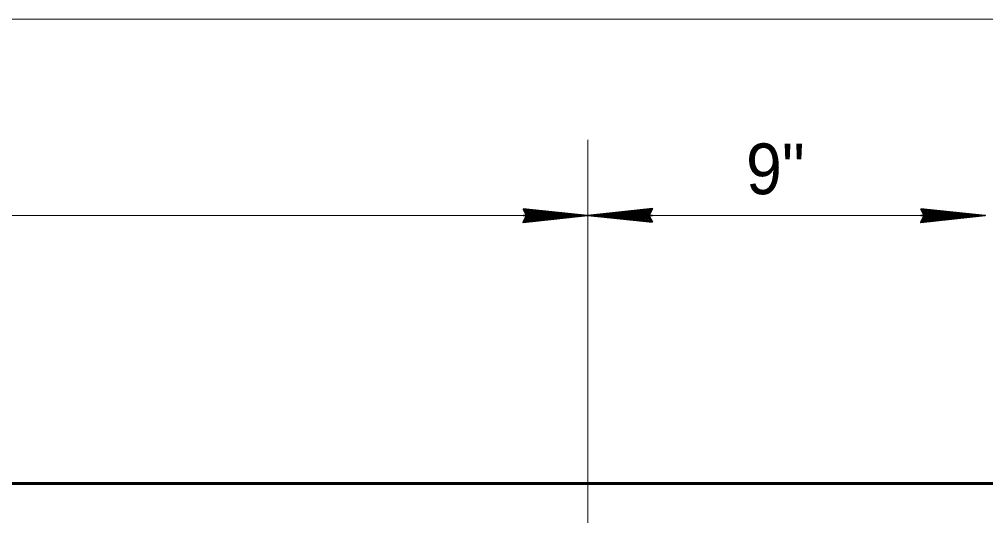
# Model space of a CAD drawing. Extents: x 6.34 to 9.53, y -1.46 to 0.53.
# Drawn here: x 7.1258 to 7.2845, y 0.2057 to 0.2884 of the extents above; entities that cross this region are included whole.
import ezdxf
from ezdxf.enums import TextEntityAlignment as Align

# ---------------------------------------------------------------- set-up
doc = ezdxf.new("R2010")
doc.units = 0
doc.header["$LTSCALE"] = 0.0033
doc.layers.add('1', color=7, linetype='Continuous', lineweight=40)

msp = doc.modelspace()

# ---------------------------------------------------------------- linework, layer by layer
at = {"layer": '1', "lineweight": 13}
for p, q in [((6.718833, 0.288417), (7.301167, 0.288417)), ((7.219167, 0.205667), (7.219167, 0.268583)), ((6.735583, 0.256167), (7.2825, 0.256167))]:
    msp.add_line(p, q, dxfattribs=at)
at = {"layer": '1', "lineweight": 35}
for p, q in [((7.2295, 0.25725), (7.222167, 0.256417)), ((7.2085, 0.256167), (7.219083, 0.256167)), ((7.208667, 0.2555), (7.216, 0.25625)), ((7.20875, 0.257167), (7.216583, 0.25625)), ((7.20875, 0.257167), (7.216583, 0.25625)), ((7.20875, 0.257083), (7.216583, 0.25625)), ((7.20875, 0.257), (7.216583, 0.256167)), ((7.20875, 0.257), (7.216583, 0.256)), ((7.20875, 0.255333), (7.216083, 0.256167)), ((7.20875, 0.25525), (7.216083, 0.256)), ((7.20875, 0.255083), (7.216083, 0.255917)), ((7.22975, 0.256167), (7.219167, 0.256167)), ((7.2295, 0.255333), (7.221667, 0.256333)), ((7.2295, 0.255333), (7.221667, 0.256167)), ((7.2295, 0.255167), (7.221667, 0.256083)), ((7.2295, 0.255167), (7.221667, 0.256083)), ((7.2295, 0.25525), (7.221667, 0.256083)), ((7.2295, 0.257083), (7.222167, 0.256333)), ((7.2295, 0.257), (7.222167, 0.256167)), ((7.229583, 0.256833), (7.22225, 0.256083)), ((7.273833, 0.256167), (7.284417, 0.256167)), ((7.274, 0.2555), (7.281333, 0.25625)), ((7.274083, 0.257167), (7.281917, 0.25625)), ((7.274083, 0.257167), (7.281917, 0.25625)), ((7.274083, 0.257083), (7.281917, 0.25625)), ((7.274083, 0.257), (7.281917, 0.256167)), ((7.274083, 0.257), (7.281917, 0.256)), ((7.274083, 0.255333), (7.281417, 0.256167)), ((7.274083, 0.25525), (7.281417, 0.256)), ((7.274083, 0.255083), (7.281417, 0.255917))]:
    msp.add_line(p, q, dxfattribs=at)
at = {"layer": '1', "lineweight": 60}
msp.add_line((6.718917, 0.212083), (7.30225, 0.212083), dxfattribs=at)
at = {"layer": '1', "lineweight": 35}
for points in [[(7.2085, 0.25725), (7.219083, 0.256167), (7.2085, 0.255), (7.209083, 0.256167)], [(7.22975, 0.255083), (7.219167, 0.256167), (7.22975, 0.257333), (7.229167, 0.256167)], [(7.273833, 0.25725), (7.284417, 0.256167), (7.273833, 0.255), (7.274417, 0.256167)], [(7.20925, 0.25625), (7.213917, 0.256333), (7.213917, 0.25625), (7.213, 0.25625), (7.20925, 0.256333), (7.21225, 0.256417), (7.209083, 0.2565), (7.211333, 0.256583), (7.209083, 0.256667), (7.212583, 0.256417), (7.21725, 0.25625), (7.216333, 0.256), (7.217583, 0.256), (7.20925, 0.256), (7.211667, 0.255833), (7.209083, 0.255833), (7.214417, 0.25625), (7.209083, 0.255583)], [(7.229, 0.256083), (7.224333, 0.256), (7.224333, 0.256083), (7.22525, 0.256083), (7.229, 0.256), (7.226, 0.255917), (7.229167, 0.255833), (7.226917, 0.25575), (7.229167, 0.255667), (7.225667, 0.255917), (7.221, 0.256083), (7.221917, 0.256333), (7.220667, 0.256333), (7.229, 0.256333), (7.226583, 0.2565), (7.229167, 0.2565), (7.223833, 0.256083), (7.229167, 0.25675)], [(7.274583, 0.25625), (7.27925, 0.256333), (7.27925, 0.25625), (7.278333, 0.25625), (7.274583, 0.256333), (7.277583, 0.256417), (7.274417, 0.2565), (7.276667, 0.256583), (7.274417, 0.256667), (7.277917, 0.256417), (7.282583, 0.25625), (7.281667, 0.256), (7.282917, 0.256), (7.274583, 0.256), (7.277, 0.255833), (7.274417, 0.255833), (7.27975, 0.25625), (7.274417, 0.255583)]]:
    msp.add_lwpolyline(points, close=True, dxfattribs=at)
for points in [[(7.20925, 0.25625), (7.208833, 0.257), (7.209083, 0.25675), (7.20925, 0.256417), (7.2095, 0.2565), (7.209333, 0.256833), (7.209167, 0.256083), (7.209, 0.255583), (7.20875, 0.255167)], [(7.229, 0.256083), (7.229417, 0.255333), (7.229167, 0.255583), (7.229, 0.255917), (7.22875, 0.255833), (7.228917, 0.2555), (7.229083, 0.25625), (7.22925, 0.25675), (7.2295, 0.257167)], [(7.274583, 0.25625), (7.274167, 0.257), (7.274417, 0.25675), (7.274583, 0.256417), (7.274833, 0.2565), (7.274667, 0.256833), (7.2745, 0.256083), (7.274333, 0.255583), (7.274083, 0.255167)]]:
    msp.add_lwpolyline(points, dxfattribs=at)

# ---------------------------------------------------------------- texts
at = {"layer": '1', "width": 0.95}
msp.add_text('9"', height=0.008334, dxfattribs=at).set_placement((7.249958, 0.259667), align=Align.CENTER)

doc.saveas('drawing.dxf')
